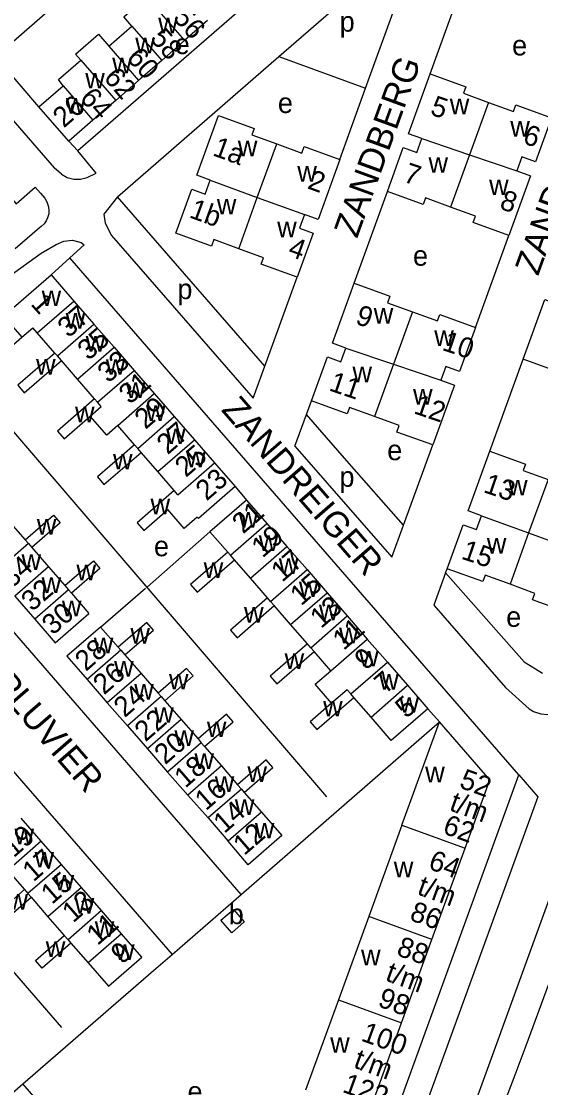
# Model space of a CAD drawing. Extents: x 155854 to 157362, y 383621 to 384685.
# Drawn here: x 156621.3 to 156723.9, y 383977 to 384187.6 of the extents above; entities that cross this region are included whole.
import ezdxf

# ---------------------------------------------------------------- set-up
doc = ezdxf.new("R2010")
doc.units = 0
for name, color, linetype in [('BLT_Basislijn', 7, 'Continuous'), ('BLT_Bebouwing', 7, 'Continuous'), ('BLT_Centroide', 7, 'Continuous'), ('BLT_Huisnummer', 7, 'Continuous'), ('BLT_Huisnummer_ tussenligend', 7, 'Continuous'), ('BLT_Huisnummer_reeks', 7, 'Continuous'), ('BLT_Onderverdeling_panden', 7, 'Continuous'), ('BLT_Straatnaam', 7, 'Continuous')]:
    doc.layers.add(name, color=color, linetype=linetype)

msp = doc.modelspace()

# ---------------------------------------------------------------- linework, layer by layer
at = {"layer": 'BLT_Basislijn'}
for p, q in [((156652.79, 384212.57), (156616.25, 384180.63)), ((156689.3, 384174.41), (156700.51, 384205.28)), ((156702.03, 384177.23), (156708.62, 384195.37)), ((156669.06, 384193.85), (156632.42, 384162.02)), ((156624.77, 384170.72), (156616.25, 384180.63)), ((156672.15, 384180.63), (156689.3, 384174.41)), ((156684.18, 384160.31), (156689.3, 384174.41)), ((156632.42, 384162.02), (156630.66, 384163.95)), ((156629.25, 384157.41), (156627.8, 384158.66)), ((156687.01, 384135.87), (156693.6, 384154.01)), ((156624.88, 384146.85), (156620.06, 384142.67)), ((156710.98, 384127.17), (156717.57, 384145.31)), ((156627.19, 384137.54), (156630.89, 384140.91)), ((156719.54, 384038.82), (156630.89, 384140.91)), ((156669.36, 384119.49), (156675.75, 384137.09)), ((156667.08, 384113.21), (156669.36, 384119.49)), ((156713.81, 384102.74), (156720.4, 384120.88)), ((156611.92, 384115.6), (156681.58, 384034.45)), ((156677.61, 384109.99), (156678.58, 384112.66)), ((156675.34, 384103.73), (156677.61, 384109.99)), ((156664.72, 384015.21), (156588.02, 384103.57)), ((156696.8, 384088.11), (156702.55, 384103.95)), ((156663.51, 384095.72), (156665.8, 384093.07)), ((156574.32, 384091.68), (156651.07, 384003.36)), ((156658.56, 384086.78), (156646.19, 384075.96)), ((156636.92, 384067.99), (156645.79, 384075.64)), ((156561.29, 384067.4), (156629.21, 383988.92)), ((156720.64, 384061.13), (156724.22, 384058.89)), ((156701.59, 384051.86), (156703.88, 384049.28)), ((156664.72, 384015.21), (156703.88, 384049.28)), ((156670.8, 383904.59), (156719.54, 384038.82)), ((156651.07, 384003.36), (156664.72, 384015.21)), ((156647.39, 384000.17), (156651.07, 384003.36)), ((156621.61, 383977.77), (156647.39, 384000.17)), ((156725.33, 383997.26), (156720.97, 383985.29)), ((156720.97, 383985.29), (156718.76, 383979.48)), ((156718.76, 383979.48), (156699.07, 383927.86))]:
    msp.add_line(p, q, dxfattribs=at)
for points in [[(156667.8, 383877.2), (156673.57, 383882.06), (156676.58, 383885.26), (156679.07, 383888.56), (156681.33, 383892.78), (156682.61, 383896.21), (156709.45, 383969.83), (156748.63, 384077.57), (156768.01, 384131.23), (156804.03, 384230.53), (156827.74, 384296.18)], [(156672.15, 384180.63), (156700.51, 384205.28)], [(156594.58, 384197.37), (156595.64, 384195.74), (156627.8, 384158.66)], [(156640.29, 384152.96), (156672.15, 384180.63)], [(156604.1, 384170.21), (156620.28, 384151.59), (156624.05, 384154.86)], [(156629.25, 384157.41), (156630.36, 384156.74), (156631.69, 384156.42), (156632.96, 384156.42), (156634.29, 384156.79), (156636.1, 384157.62), (156632.42, 384162.02)], [(156624.05, 384154.86), (156625.09, 384153.67), (156625.9, 384152.7), (156626.33, 384151.97), (156626.6, 384151.19), (156626.73, 384150.42), (156626.71, 384149.58), (156626.49, 384148.83), (156626.17, 384148.21), (156625.77, 384147.65), (156625.18, 384147.09), (156624.88, 384146.85)], [(156640.29, 384152.96), (156637.61, 384149.51), (156637.84, 384147.72), (156639.09, 384145.32), (156667.08, 384113.21)], [(156669.36, 384119.49), (156640.29, 384152.96)], [(156584.12, 384100.34), (156583.27, 384101.67), (156583.03, 384102.74), (156583.32, 384104.62), (156584.26, 384106.07), (156605.59, 384125.67), (156618.83, 384137.21), (156625.18, 384141.83), (156628.2, 384143.52), (156629.66, 384144.19), (156631.41, 384144.42), (156633.12, 384143.94), (156633.68, 384143.45), (156630.89, 384140.91)], [(156681.55, 384105.45), (156677.61, 384109.99)], [(156686.06, 384100.27), (156681.55, 384105.45)], [(156675.34, 384103.73), (156694.49, 384081.77), (156696.8, 384088.11)], [(156696.8, 384088.11), (156686.06, 384100.27)], [(156705.09, 384078.73), (156705.38, 384079.52)], [(156705.09, 384078.73), (156702.76, 384072.29), (156716.91, 384056.05), (156721.63, 384051.83), (156722.48, 384051.3), (156723.9, 384050.83), (156725.32, 384050.72), (156726.84, 384051.03), (156727.91, 384051.45), (156728.98, 384052.18), (156729.93, 384053.23), (156730.68, 384054.64)], [(156720.64, 384061.13), (156705.09, 384078.73)], [(156719.54, 384038.82), (156723.34, 384034.44), (156677.59, 383908.65)]]:
    msp.add_lwpolyline(points, dxfattribs=at)
at = {"layer": 'BLT_Bebouwing'}
for p, q in [((156658.06, 384187.75), (156653.53, 384183.81)), ((156653.53, 384183.81), (156649.02, 384179.89)), ((156649.02, 384179.89), (156644.46, 384175.93)), ((156644.46, 384175.93), (156639.94, 384172)), ((156639.94, 384172), (156635.41, 384168.07)), ((156630.66, 384163.95), (156624.77, 384170.72)), ((156635.41, 384168.07), (156630.66, 384163.95)), ((156617.79, 384129.37), (156627.19, 384137.54)), ((156627.19, 384137.54), (156631.67, 384132.38)), ((156631.67, 384132.38), (156635.64, 384127.81)), ((156635.64, 384127.81), (156639.61, 384123.24)), ((156621.4, 384125.21), (156623.57, 384127.09)), ((156624.44, 384126.09), (156623.57, 384127.09)), ((156627.9, 384122.11), (156624.44, 384126.09)), ((156612, 384117.05), (156621.4, 384125.21)), ((156639.61, 384123.24), (156643.57, 384118.67)), ((156632.38, 384116.96), (156629.21, 384120.6)), ((156635.77, 384113.05), (156632.38, 384116.96)), ((156643.57, 384118.67), (156647.54, 384114.11)), ((156647.54, 384114.11), (156651.51, 384109.54)), ((156651.51, 384109.54), (156655.47, 384104.97)), ((156643.64, 384104), (156640.36, 384107.78)), ((156655.47, 384104.97), (156659.44, 384100.4)), ((156648.25, 384098.69), (156644.95, 384102.49)), ((156659.44, 384100.4), (156663.51, 384095.72)), ((156651.51, 384094.94), (156648.25, 384098.69)), ((156663.51, 384095.72), (156656.26, 384089.42)), ((156665.8, 384093.07), (156658.56, 384086.78)), ((156665.8, 384093.07), (156669.81, 384088.46)), ((156653.44, 384087.44), (156650.23, 384091.19)), ((156618.71, 384089.04), (156622.03, 384085.22)), ((156669.81, 384088.46), (156673.77, 384083.9)), ((156662.06, 384082.79), (156658.56, 384086.78)), ((156623.34, 384083.71), (156626.65, 384079.91)), ((156673.77, 384083.9), (156677.74, 384079.33)), ((156666.56, 384077.62), (156663.38, 384081.28)), ((156626.65, 384079.91), (156629.89, 384076.17)), ((156677.74, 384079.33), (156681.71, 384074.76)), ((156669.93, 384073.74), (156666.56, 384077.62)), ((156619.98, 384074.11), (156623.95, 384069.55)), ((156631.2, 384074.66), (156634.64, 384070.64)), ((156681.71, 384074.76), (156685.67, 384070.19)), ((156628, 384064.88), (156634.64, 384070.64)), ((156674.49, 384068.49), (156671.25, 384072.23)), ((156623.95, 384069.55), (156628, 384064.88)), ((156677.8, 384064.68), (156674.49, 384068.49)), ((156685.67, 384070.19), (156689.64, 384065.62)), ((156636.92, 384067.99), (156630.29, 384062.24)), ((156636.92, 384067.99), (156640.43, 384064.02)), ((156689.64, 384065.62), (156693.61, 384061.05)), ((156630.29, 384062.24), (156634.3, 384057.62)), ((156641.74, 384062.52), (156644.94, 384058.84)), ((156682.43, 384059.36), (156679.11, 384063.17)), ((156693.61, 384061.05), (156697.57, 384056.49)), ((156644.94, 384058.84), (156648.32, 384054.95)), ((156634.3, 384057.62), (156638.27, 384053.05)), ((156697.57, 384056.49), (156701.59, 384051.86)), ((156690.37, 384050.22), (156686.99, 384054.11)), ((156638.27, 384053.05), (156642.24, 384048.49)), ((156649.63, 384053.44), (156652.87, 384049.71)), ((156701.59, 384051.86), (156694.36, 384045.62)), ((156652.87, 384049.71), (156656.19, 384045.89)), ((156694.36, 384045.62), (156690.37, 384050.22)), ((156642.24, 384048.49), (156646.21, 384043.92)), ((156713.85, 384037.83), (156703.88, 384049.28)), ((156646.21, 384043.92), (156650.18, 384039.35)), ((156657.5, 384044.38), (156660.8, 384040.57)), ((156650.18, 384039.35), (156654.15, 384034.79)), ((156660.8, 384040.57), (156664.02, 384036.86)), ((156708.95, 384024.33), (156713.85, 384037.83)), ((156654.15, 384034.79), (156658.2, 384030.29)), ((156665.33, 384035.35), (156668.74, 384031.43)), ((156668.74, 384031.43), (156672.73, 384026.81)), ((156625.23, 384025.68), (156621.26, 384030.25)), ((156658.2, 384030.29), (156662.17, 384025.72)), ((156696.47, 384028.87), (156689.92, 384010.84)), ((156672.73, 384026.81), (156666.1, 384021.05)), ((156629.2, 384021.12), (156625.23, 384025.68)), ((156666.1, 384021.05), (156662.17, 384025.72)), ((156702.41, 384006.31), (156708.95, 384024.33)), ((156633.16, 384016.55), (156629.2, 384021.12)), ((156618.61, 384019.93), (156621.91, 384016.14)), ((156637.13, 384011.99), (156633.16, 384016.55)), ((156623.22, 384014.63), (156626.54, 384010.8)), ((156641.1, 384007.42), (156637.13, 384011.99)), ((156626.54, 384010.8), (156629.77, 384007.08)), ((156689.92, 384010.84), (156683.92, 383994.35)), ((156645.12, 384002.81), (156641.1, 384007.42)), ((156631.09, 384005.57), (156634.48, 384001.67)), ((156696.42, 383989.81), (156702.41, 384006.31)), ((156634.48, 384001.67), (156638.49, 383997.05)), ((156638.49, 383997.05), (156645.12, 384002.81)), ((156683.92, 383994.35), (156677.45, 383976.53)), ((156689.95, 383971.99), (156696.42, 383989.81)), ((156634.83, 383962.56), (156621.61, 383977.77))]:
    msp.add_line(p, q, dxfattribs=at)
for points in [[(156643.13, 384186.67), (156641.51, 384188.52), (156646.04, 384192.44), (156646.64, 384191.74)], [(156638.57, 384182.71), (156643.13, 384186.67)], [(156633.04, 384179.94), (156632.01, 384181.14), (156636.54, 384185.07), (156638.57, 384182.71)], [(156629.53, 384174.85), (156628.62, 384176.1), (156633.04, 384179.94)], [(156700.42, 384164.45), (156697.74, 384165.42), (156702.03, 384177.23)], [(156702.03, 384177.23), (156709.08, 384174.67), (156708.62, 384173.4), (156713.55, 384171.61)], [(156624.77, 384170.72), (156629.53, 384174.85)], [(156713.55, 384171.61), (156718.49, 384169.82), (156718.95, 384171.09), (156726, 384168.53)], [(156658.61, 384156.23), (156655.93, 384157.2), (156660.21, 384169.01), (156667.26, 384166.45), (156666.8, 384165.18), (156671.74, 384163.39)], [(156726, 384168.53), (156722.85, 384159.84), (156720.17, 384160.82), (156719.18, 384158.09)], [(156671.74, 384163.39), (156676.67, 384161.6), (156677.13, 384162.87), (156684.18, 384160.31)], [(156693.6, 384154.01), (156696.75, 384162.7), (156699.43, 384161.73), (156700.42, 384164.45)], [(156684.18, 384160.31), (156679.9, 384148.5), (156677.22, 384149.47)], [(156719.18, 384158.09), (156721.86, 384157.12), (156717.57, 384145.31)], [(156664.23, 384142.71), (156659.29, 384144.5), (156658.83, 384143.23), (156651.78, 384145.79), (156654.94, 384154.48), (156657.62, 384153.5), (156658.61, 384156.23)], [(156706.05, 384150.93), (156701.11, 384152.72), (156700.65, 384151.45), (156693.6, 384154.01)], [(156717.57, 384145.31), (156717.57, 384145.31), (156710.52, 384147.87), (156710.98, 384149.14), (156706.05, 384150.93)], [(156677.22, 384149.47), (156676.23, 384146.75), (156678.91, 384145.77), (156675.75, 384137.09)], [(156675.75, 384137.09), (156668.7, 384139.65), (156669.16, 384140.92), (156664.23, 384142.71)], [(156685.41, 384123.09), (156682.73, 384124.07), (156687.01, 384135.87)], [(156687.01, 384135.87), (156694.06, 384133.31), (156693.6, 384132.04), (156698.54, 384130.25)], [(156720.4, 384120.88), (156724.69, 384132.68), (156727.37, 384131.71)], [(156698.54, 384130.25), (156703.47, 384128.46), (156703.93, 384129.73), (156710.98, 384127.17)], [(156710.98, 384127.17), (156707.83, 384118.48), (156705.15, 384119.46), (156704.16, 384116.73)], [(156627.9, 384122.11), (156620.57, 384115.74), (156621.88, 384114.23), (156629.21, 384120.6)], [(156678.58, 384112.66), (156681.74, 384121.34), (156684.42, 384120.37), (156685.41, 384123.09)], [(156732.84, 384117.79), (156727.91, 384119.59), (156727.45, 384118.32), (156720.4, 384120.88)], [(156704.16, 384116.73), (156704.16, 384116.73), (156706.84, 384115.76), (156702.55, 384103.95)], [(156635.77, 384113.05), (156628.44, 384106.68), (156629.75, 384105.17), (156634.89, 384109.64)], [(156691.03, 384109.57), (156686.09, 384111.37), (156685.63, 384110.1), (156678.58, 384112.66)], [(156640.36, 384107.78), (156638.17, 384105.87), (156634.89, 384109.64)], [(156702.55, 384103.95), (156695.5, 384106.51), (156695.96, 384107.78), (156691.03, 384109.57)], [(156643.64, 384104), (156636.31, 384097.63), (156637.62, 384096.12), (156644.95, 384102.49)], [(156712.21, 384089.96), (156709.53, 384090.93), (156713.81, 384102.74)], [(156713.81, 384102.74), (156713.81, 384102.74), (156720.86, 384100.18), (156720.4, 384098.91), (156725.34, 384097.12)], [(156651.51, 384094.94), (156644.18, 384088.58), (156645.49, 384087.07), (156650.23, 384091.19)], [(156622.03, 384085.22), (156627.65, 384090.11), (156628.97, 384088.6), (156623.34, 384083.71)], [(156656.26, 384089.42), (156656.05, 384089.66), (156653.44, 384087.44)], [(156705.38, 384079.52), (156708.54, 384088.2), (156711.22, 384087.23), (156712.21, 384089.96)], [(156662.06, 384082.79), (156654.73, 384076.42), (156656.04, 384074.91), (156663.38, 384081.28)], [(156629.89, 384076.17), (156635.52, 384081.06), (156636.83, 384079.55), (156631.2, 384074.66)], [(156717.83, 384076.44), (156712.89, 384078.23), (156712.43, 384076.96), (156705.38, 384079.52)], [(156729.35, 384070.82), (156722.3, 384073.38), (156722.76, 384074.64), (156717.83, 384076.44)], [(156669.93, 384073.74), (156662.6, 384067.36), (156663.91, 384065.85), (156671.25, 384072.23)], [(156641.74, 384062.52), (156647.37, 384067.41), (156646.05, 384068.92), (156640.43, 384064.02)], [(156677.8, 384064.68), (156670.47, 384058.3), (156671.78, 384056.8), (156679.11, 384063.17)], [(156649.63, 384053.44), (156655.26, 384058.33), (156653.95, 384059.84), (156648.32, 384054.95)], [(156682.59, 384052.95), (156679.33, 384056.73), (156682.43, 384059.36)], [(156682.59, 384052.95), (156678.34, 384049.25), (156679.65, 384047.74), (156686.99, 384054.11)], [(156657.5, 384044.38), (156663.13, 384049.28), (156661.82, 384050.79), (156656.19, 384045.89)], [(156696.47, 384028.87), (156703.88, 384049.28)], [(156665.33, 384035.35), (156670.97, 384040.26), (156669.66, 384041.77), (156664.02, 384036.86)], [(156621.91, 384016.14), (156616.23, 384011.21), (156617.54, 384009.7), (156623.22, 384014.63)], [(156631.09, 384005.57), (156625.41, 384000.64), (156624.1, 384002.15), (156629.77, 384007.08)], [(156611.96, 383969.4), (156621.61, 383977.77)]]:
    msp.add_lwpolyline(points, dxfattribs=at)
msp.add_lwpolyline([(156660.73, 384010.09), (156663.21, 384012.23), (156665.34, 384009.76), (156662.86, 384007.62)], close=True, dxfattribs=at)
at = {"layer": 'BLT_Onderverdeling_panden'}
for p, q in [((156646.64, 384191.74), (156653.53, 384183.81)), ((156643.13, 384186.67), (156649.02, 384179.89)), ((156638.57, 384182.71), (156644.46, 384175.93)), ((156633.04, 384179.94), (156639.94, 384172)), ((156629.53, 384174.85), (156635.41, 384168.07)), ((156713.55, 384171.61), (156709.8, 384161.27)), ((156667.91, 384152.85), (156671.74, 384163.39)), ((156700.42, 384164.45), (156709.8, 384161.27)), ((156709.8, 384161.27), (156706.05, 384150.93)), ((156709.8, 384161.27), (156719.18, 384158.09)), ((156658.61, 384156.23), (156667.91, 384152.85)), ((156664.23, 384142.71), (156667.91, 384152.85)), ((156667.91, 384152.85), (156677.22, 384149.47)), ((156624.44, 384126.09), (156631.67, 384132.38)), ((156698.54, 384130.25), (156694.78, 384119.91)), ((156617.79, 384129.37), (156621.4, 384125.21)), ((156628.41, 384121.53), (156635.64, 384127.81)), ((156632.38, 384116.96), (156639.61, 384123.24)), ((156628.41, 384121.53), (156627.9, 384122.11)), ((156629.21, 384120.6), (156628.41, 384121.53)), ((156685.41, 384123.09), (156694.78, 384119.91)), ((156694.78, 384119.91), (156691.03, 384109.57)), ((156694.78, 384119.91), (156704.16, 384116.73)), ((156636.35, 384112.39), (156643.57, 384118.67)), ((156636.35, 384112.39), (156635.77, 384113.05)), ((156640.36, 384107.78), (156647.54, 384114.11)), ((156644.28, 384103.26), (156651.51, 384109.54)), ((156648.25, 384098.69), (156655.47, 384104.97)), ((156644.28, 384103.26), (156643.64, 384104)), ((156644.95, 384102.49), (156644.28, 384103.26)), ((156652.22, 384094.12), (156659.44, 384100.4)), ((156725.34, 384097.12), (156721.51, 384086.58)), ((156652.22, 384094.12), (156651.51, 384094.94)), ((156712.21, 384089.96), (156721.51, 384086.58)), ((156662.59, 384082.19), (156669.81, 384088.46)), ((156721.51, 384086.58), (156717.83, 384076.44)), ((156721.51, 384086.58), (156730.81, 384083.2)), ((156622.68, 384084.48), (156616.01, 384078.68)), ((156622.03, 384085.22), (156622.68, 384084.48)), ((156622.68, 384084.48), (156623.34, 384083.71)), ((156666.56, 384077.62), (156673.77, 384083.9)), ((156662.59, 384082.19), (156662.06, 384082.79)), ((156663.38, 384081.28), (156662.59, 384082.19)), ((156626.65, 384079.91), (156619.98, 384074.11)), ((156670.52, 384073.05), (156677.74, 384079.33)), ((156630.61, 384075.34), (156623.95, 384069.55)), ((156629.89, 384076.17), (156630.61, 384075.34)), ((156630.61, 384075.34), (156631.2, 384074.66)), ((156670.52, 384073.05), (156669.93, 384073.74)), ((156671.25, 384072.23), (156670.52, 384073.05)), ((156674.49, 384068.49), (156681.71, 384074.76)), ((156678.46, 384063.92), (156685.67, 384070.19)), ((156678.46, 384063.92), (156677.8, 384064.68)), ((156682.43, 384059.36), (156689.64, 384065.62)), ((156640.97, 384063.41), (156634.3, 384057.62)), ((156640.43, 384064.02), (156640.97, 384063.41)), ((156640.97, 384063.41), (156641.74, 384062.52)), ((156679.11, 384063.17), (156678.46, 384063.92)), ((156686.4, 384054.79), (156693.61, 384061.05)), ((156644.94, 384058.84), (156638.27, 384053.05)), ((156690.37, 384050.22), (156697.57, 384056.49)), ((156648.9, 384054.27), (156642.24, 384048.49)), ((156648.32, 384054.95), (156648.9, 384054.27)), ((156648.9, 384054.27), (156649.63, 384053.44)), ((156686.4, 384054.79), (156685.67, 384055.62)), ((156686.99, 384054.11), (156686.4, 384054.79)), ((156652.87, 384049.71), (156646.21, 384043.92)), ((156656.19, 384045.89), (156656.84, 384045.14)), ((156656.84, 384045.14), (156650.18, 384039.35)), ((156656.84, 384045.14), (156657.5, 384044.38)), ((156660.8, 384040.57), (156654.15, 384034.79)), ((156664.77, 384036), (156658.2, 384030.29)), ((156664.02, 384036.86), (156664.77, 384036)), ((156664.77, 384036), (156665.33, 384035.35)), ((156668.74, 384031.43), (156662.17, 384025.72)), ((156696.47, 384028.87), (156708.95, 384024.33)), ((156625.23, 384025.68), (156618.61, 384019.93)), ((156629.2, 384021.12), (156622.57, 384015.37)), ((156621.91, 384016.14), (156622.57, 384015.37)), ((156633.16, 384016.55), (156626.54, 384010.8)), ((156622.57, 384015.37), (156623.22, 384014.63)), ((156637.13, 384011.99), (156630.51, 384006.23)), ((156702.41, 384006.31), (156689.92, 384010.84)), ((156641.1, 384007.42), (156634.48, 384001.67)), ((156629.77, 384007.08), (156630.51, 384006.23)), ((156630.51, 384006.23), (156631.09, 384005.57)), ((156683.92, 383994.35), (156696.42, 383989.81))]:
    msp.add_line(p, q, dxfattribs=at)
for points in [[(156634.89, 384109.64), (156637.08, 384111.54), (156636.35, 384112.39)], [(156685.67, 384055.62), (156682.59, 384052.95)]]:
    msp.add_lwpolyline(points, dxfattribs=at)

# ---------------------------------------------------------------- texts
at = {"layer": 'BLT_Centroide'}
for s, p in [('p', (156684.17, 384185.57)), ('w', (156648.33, 384185.23)), ('w', (156643.8, 384181.3)), ('e', (156651.59, 384181.14)), ('e', (156718.24, 384180.87)), ('w', (156639.25, 384177.34)), ('w', (156633.92, 384174.36)), ('w', (156630.09, 384169.39)), ('e', (156671.97, 384169.5)), ('w', (156705.92, 384169.25)), ('w', (156717.88, 384164.84)), ('w', (156664.06, 384160.94)), ('w', (156701.72, 384157.69)), ('w', (156675.81, 384155.94)), ('w', (156713.69, 384153.28)), ('w', (156659.91, 384149.47)), ('w', (156671.83, 384144.97)), ('e', (156698.66, 384139.34)), ('p', (156652.12, 384132.74)), ('w', (156625.3, 384131.38)), ('w', (156630.05, 384126.94)), ('w', (156690.9, 384127.91)), ('w', (156634.01, 384122.38)), ('w', (156702.86, 384123.5)), ('w', (156624.2, 384117.86)), ('w', (156637.98, 384117.81)), ('w', (156686.7, 384116.34)), ('w', (156641.94, 384113.25)), ('w', (156698.67, 384111.94)), ('w', (156631.89, 384108.45)), ('w', (156645.91, 384108.69)), ('w', (156649.88, 384104.12)), ('w', (156639.4, 384099.12)), ('w', (156653.84, 384099.53)), ('e', (156693.57, 384100.94)), ('p', (156684.13, 384095.69)), ('w', (156717.44, 384093.98)), ('w', (156646.82, 384090.25)), ('w', (156664.2, 384087.62)), ('w', (156624.35, 384086.26)), ('w', (156668.19, 384083.03)), ('w', (156713.25, 384082.5)), ('e', (156647.49, 384081.97)), ('w', (156621.33, 384079.28)), ('w', (156672.15, 384078.47)), ('w', (156632.18, 384077.21)), ('w', (156657.32, 384077.67)), ('w', (156625.3, 384074.72)), ('w', (156676.12, 384073.91)), ('w', (156629.31, 384070.12)), ('w', (156665.29, 384068.87)), ('w', (156680.08, 384069.34)), ('e', (156717.07, 384068.03)), ('w', (156642.84, 384064.73)), ('w', (156684.05, 384064.78)), ('w', (156635.6, 384062.81)), ('w', (156673.31, 384059.71)), ('w', (156688.02, 384060.22)), ('w', (156639.62, 384058.22)), ('w', (156650.45, 384055.68)), ('w', (156691.98, 384055.62)), ('w', (156643.59, 384053.66)), ('w', (156695.98, 384051.06)), ('w', (156647.55, 384049.09)), ('w', (156680.91, 384050.35)), ('w', (156651.53, 384044.53)), ('w', (156657.95, 384046.27)), ('w', (156655.49, 384039.97)), ('w', (156665.96, 384037.42)), ('w', (156701.07, 384037.32)), ('w', (156659.5, 384035.44)), ('w', (156663.47, 384030.88)), ('w', (156667.42, 384026.25)), ('w', (156619.93, 384025.09)), ('w', (156623.9, 384020.53)), ('w', (156694.87, 384018.56)), ('w', (156627.87, 384015.97)), ('w', (156618.75, 384012.2)), ('w', (156631.84, 384011.41)), ('b', (156662.26, 384009.32)), ('w', (156635.8, 384006.81)), ('w', (156626.12, 384002.84)), ('w', (156639.8, 384002.25)), ('w', (156688.4, 384001.2)), ('w', (156682.3, 383983.93)), ('e', (156654.12, 383974.26))]:
    msp.add_text(s, height=4, dxfattribs=at).set_placement(p)
at = {"layer": 'BLT_Huisnummer'}
for s, rotation, p in [('56', 310.9857, (156651.08, 384188.23)), ('60', 310.9857, (156641.92, 384180.3)), ('26', 41.0538, (156629.69, 384166.43)), ('5', 341.2588, (156701.86, 384169.26)), ('6', 341.2588, (156720.14, 384163.59)), ('1a', 340.0435, (156658.89, 384161.19)), ('7', 341.2588, (156696.55, 384156)), ('2', 340.0435, (156677.62, 384154.67)), ('8', 341.2588, (156715.57, 384150.66)), ('1b', 340.0435, (156654.27, 384148.94)), ('4', 340.0435, (156673.76, 384141.38)), ('1', 312.0198, (156622.99, 384131.7)), ('37', 40.9834, (156630.62, 384124.95)), ('9', 341.2588, (156687.08, 384127.94)), ('10', 341.2588, (156704.22, 384122.76)), ('33', 40.9834, (156638.49, 384116.04)), ('11', 341.2588, (156681.87, 384114.77)), ('29', 40.9834, (156645.82, 384106.9)), ('12', 341.2588, (156698.61, 384110.25)), ('27', 40.9834, (156650.2, 384101.9)), ('23', 40.9834, (156657.89, 384092.77)), ('13', 341.2588, (156712.38, 384094.67)), ('21', 40.9834, (156665.1, 384086.26)), ('17', 40.9834, (156672.8, 384076.71)), ('15', 341.2588, (156708.01, 384081.54)), ('34', 40.9869, (156619.39, 384075.53)), ('13', 40.9834, (156680.5, 384067.57)), ('30', 40.9869, (156627.52, 384066.25)), ('28', 40.9869, (156634.05, 384059.11)), ('9', 40.9834, (156689.29, 384059.32)), ('24', 40.9869, (156641.71, 384049.97)), ('5', 40.9834, (156697.31, 384049.81)), ('20', 40.9869, (156649.72, 384040.69)), ('16', 40.9869, (156657.74, 384031.58)), ('12', 40.9869, (156665.31, 384022.74)), ('17', 40.9728, (156623.68, 384017.54)), ('13', 40.9728, (156631.52, 384009.44)), ('9', 40.9728, (156641.15, 384001.25))]:
    msp.add_text(s, height=4, rotation=rotation, dxfattribs=at).set_placement(p)
at = {"layer": 'BLT_Huisnummer_ tussenligend'}
for s, rotation, p in [('58', 310.9857, (156646.54, 384184.14)), ('62', 310.9857, (156637.39, 384176.36)), ('64', 310.9857, (156632.68, 384172.37)), ('35', 40.9834, (156634.55, 384120.49)), ('31', 40.9834, (156642.72, 384111.82)), ('25', 40.9834, (156653.8, 384097.41)), ('19', 40.9834, (156668.93, 384081.51)), ('32', 40.9869, (156623.43, 384070.92)), ('15', 40.9834, (156676.55, 384072.04)), ('11', 40.9834, (156684.95, 384063.24)), ('26', 40.9869, (156637.63, 384054.47)), ('7', 40.9834, (156693.2, 384054.65)), ('22', 40.9869, (156645.82, 384045.2)), ('18', 40.9869, (156653.67, 384036.04)), ('14', 40.9869, (156661.39, 384027.1)), ('19', 40.9728, (156619.77, 384022.31)), ('15', 40.9728, (156627.33, 384013.08)), ('11', 40.9728, (156636.33, 384004.98))]:
    msp.add_text(s, height=4, rotation=rotation, dxfattribs=at).set_placement(p)
at = {"layer": 'BLT_Huisnummer_reeks'}
for s, p in [('52', (156707.61, 384036.35)), ('t/m', (156705.64, 384031.87)), ('62', (156704.32, 384027.32)), ('64', (156701.48, 384020.31)), ('t/m', (156699.28, 384015.29)), ('86', (156697.79, 384010.2)), ('88', (156695.2, 384003.27)), ('t/m', (156693, 383998.26)), ('98', (156691.51, 383993.17)), ('100', (156688.2, 383986.37)), ('t/m', (156686.71, 383981.09)), ('122', (156684.52, 383976.25))]:
    msp.add_text(s, height=4, rotation=340.0266, dxfattribs=at).set_placement(p)
at = {"layer": 'BLT_Straatnaam'}
for s, rotation, p in [('ZANDGROEVE', 70.0435, (156723.38, 384137.2)), ('ZANDBERG', 70.0435, (156687.62, 384144.62)), ('ZANDREIGER', 310.9812, (156660.63, 384110.81)), ('ZANDPLUVIER', 310.983, (156603.45, 384070.27))]:
    msp.add_text(s, height=5, rotation=rotation, dxfattribs=at).set_placement(p)

doc.saveas('drawing.dxf')
